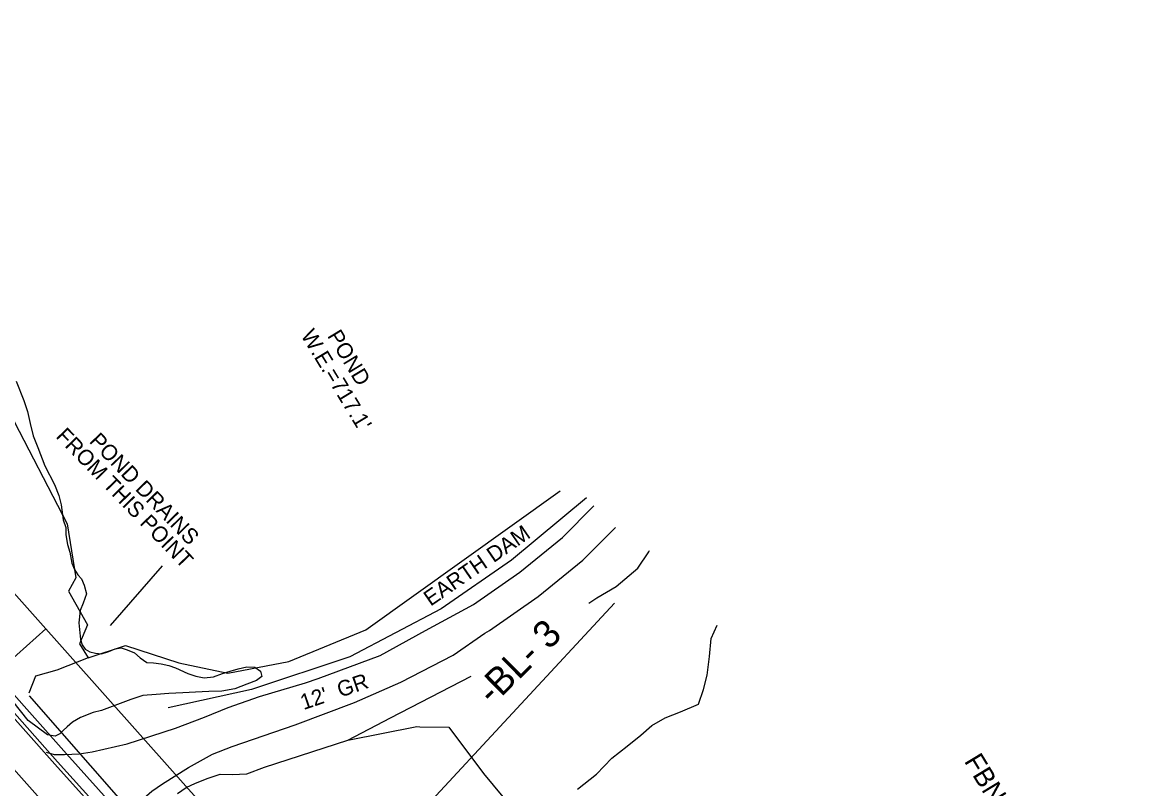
# Model space of a CAD drawing. Extents: x 1498375 to 1499839, y 700490 to 702854.
# Drawn here: x 1498616.6 to 1498900.7, y 702558.4 to 702754.8 of the extents above; entities that cross this region are included whole.
import ezdxf

# ---------------------------------------------------------------- set-up
doc = ezdxf.new("R2010")
doc.units = 0
for name, color, linetype in [('Exist Horizontal Alignment', 7, 'Continuous'), ('Exist Horizontal Baseline Alignment Station Label', 7, 'Continuous'), ('Exist Hydro Stream or Body of Water', 7, 'Continuous'), ('Exist Hydro Stream or Body of Water Leader', 7, 'Continuous'), ('Exist Hydro Stream or Body of Water Text', 7, 'Continuous'), ('Exist Other Culture Dam', 7, 'Continuous'), ('Exist Other Culture Dam Text', 7, 'Continuous'), ('Exist Property Owner Text', 7, 'Continuous'), ('Exist Right of Way Line', 7, 'Continuous'), ('Exist Right of Way Width CELL', 7, 'Continuous'), ('Exist Roads EOP', 7, 'Continuous'), ('Exist Roads Soil', 7, 'Continuous'), ('Exist Roads Soil Text', 7, 'Continuous'), ('Exist Structure Minor Pipes RCP 15 Inch', 7, 'Continuous'), ('Exist Utilities Telephone UG Cable', 7, 'Continuous'), ('Exist Vegetation Hedge Row', 7, 'Continuous'), ('Exist Vegetation Woods Line', 7, 'Continuous')]:
    doc.layers.add(name, color=color, linetype=linetype)

msp = doc.modelspace()

# ---------------------------------------------------------------- linework, layer by layer
at = {"layer": 'Exist Horizontal Alignment'}
msp.add_line((1498462.01, 702734.88), (1498796.99, 702358.25), dxfattribs=at)
at = {"layer": 'Exist Horizontal Baseline Alignment Station Label'}
msp.add_line((1498656.97, 702485.84), (1498768.4, 702605.94), dxfattribs=at)
at = {"layer": 'Exist Hydro Stream or Body of Water'}
for points in [[(1498613.4, 702654.84), (1498628.21, 702626.31), (1498630.4, 702612.48), (1498628.51, 702609.01), (1498633.37, 702600.4), (1498631.33, 702595.51), (1498633.57, 702592), (1498643.13, 702595.13), (1498656.81, 702590.65), (1498669.3, 702588.07), (1498684.93, 702591), (1498704.71, 702599.15), (1498754.44, 702634.77)], [(1498633.57, 702592), (1498625.53, 702588.81), (1498620.02, 702587.23), (1498618.32, 702582.91)]]:
    msp.add_lwpolyline(points, dxfattribs=at)
at = {"layer": 'Exist Hydro Stream or Body of Water Leader'}
msp.add_lwpolyline([(1498639.27, 702600.23), (1498652.59, 702615.54)], dxfattribs=at)
at = {"layer": 'Exist Other Culture Dam'}
msp.add_lwpolyline([(1498761.24, 702632.94), (1498741.99, 702616.94), (1498723.98, 702604.49), (1498700.61, 702592.2), (1498675.42, 702583.88), (1498654.01, 702579.14)], dxfattribs=at)
at = {"layer": 'Exist Right of Way Line'}
msp.add_line((1498484.43, 702754.82), (1498819.41, 702378.18), dxfattribs=at)
at = {"layer": 'Exist Right of Way Width CELL'}
msp.add_line((1498622.69, 702599.36), (1498600.43, 702579.56), dxfattribs=at)
at = {"layer": 'Exist Roads EOP'}
msp.add_lwpolyline([(1498653.88, 702532.59), (1498624.99, 702564.68), (1498593.83, 702599.75), (1498561.87, 702636.22), (1498531.52, 702670.43), (1498499.26, 702706.7), (1498468.51, 702741.33)], dxfattribs=at)
at = {"layer": 'Exist Roads Soil'}
for points in [[(1498692.47, 702586.65), (1498708.37, 702592.53), (1498719.94, 702598.93), (1498732.28, 702605.63), (1498744.17, 702613.89), (1498755.03, 702622.79), (1498763.13, 702630.86)], [(1498735.15, 702598.32), (1498736.37, 702598.99), (1498748.87, 702607.66), (1498760.26, 702617.01), (1498768.6, 702625.31)], [(1498670.43, 702569.26), (1498686.6, 702574.77), (1498701.79, 702580.51), (1498713.64, 702585.7), (1498727.03, 702592.63), (1498735.15, 702598.32)], [(1498655.94, 702573.98), (1498663.34, 702576.75), (1498669.42, 702579.25), (1498677.43, 702582.02), (1498689.24, 702585.54), (1498692.47, 702586.65)], [(1498622.8, 702567.82), (1498624.83, 702567.19), (1498627.52, 702567.22), (1498631.23, 702567.33), (1498634.55, 702567.84), (1498643.57, 702569.94), (1498655.94, 702573.98)], [(1498644.48, 702543.72), (1498644.29, 702549), (1498645.31, 702552.27), (1498647.18, 702555.48), (1498649.83, 702557.76), (1498652.61, 702559.64), (1498659.23, 702563.88), (1498665.42, 702567.32), (1498670.43, 702569.26)]]:
    msp.add_lwpolyline(points, dxfattribs=at)
at = {"layer": 'Exist Structure Minor Pipes RCP 15 Inch'}
msp.add_lwpolyline([(1498618.47, 702582.21), (1498649.73, 702546.53)], dxfattribs=at)
at = {"layer": 'Exist Utilities Telephone UG Cable'}
for points in [[(1498478.31, 702731.8), (1498500, 702707.36), (1498532.27, 702671.1), (1498562.62, 702636.88), (1498594.58, 702600.41), (1498625.73, 702565.35), (1498657.7, 702529.85)], [(1498480.79, 702733.52), (1498502.24, 702709.35), (1498534.51, 702673.09), (1498564.87, 702638.87), (1498596.83, 702602.4), (1498627.97, 702567.35), (1498660.83, 702530.85), (1498690.32, 702497.9), (1498721.99, 702462.5), (1498751.79, 702428.93), (1498785.03, 702390.83)]]:
    msp.add_lwpolyline(points, dxfattribs=at)
at = {"layer": 'Exist Vegetation Hedge Row'}
for points in [[(1498761.83, 702605.97), (1498763.85, 702607.3), (1498768.85, 702610.24), (1498774.32, 702614.93), (1498777.14, 702619.09), (1498777.35, 702619.42)], [(1498700.08, 702570.87), (1498711.04, 702576.62), (1498731.64, 702587.23)]]:
    msp.add_lwpolyline(points, dxfattribs=at)
at = {"layer": 'Exist Vegetation Woods Line'}
for points in [[(1498615.13, 702662.82), (1498617.04, 702657.89), (1498618.05, 702655.06), (1498618.67, 702652.02), (1498619.48, 702648.86), (1498620.64, 702645.83), (1498622.44, 702641.18), (1498624.95, 702636.41), (1498626.08, 702633.52), (1498626.62, 702631.16), (1498627.15, 702627.28), (1498627.85, 702625.39), (1498627.79, 702623.48), (1498628.28, 702621.01), (1498628.84, 702619.01), (1498629.38, 702616.19), (1498630.01, 702614.56), (1498630.91, 702613.24), (1498631.83, 702612.21), (1498632.49, 702610.56), (1498633.09, 702608.34), (1498632.31, 702605.94), (1498631.53, 702604.05), (1498631.2, 702600.96), (1498631.6, 702596.65), (1498632.05, 702595.29), (1498632.75, 702594.21), (1498634.02, 702593.52), (1498635.46, 702593.13), (1498637, 702593), (1498638.82, 702593.62), (1498640.51, 702594.28), (1498642, 702594.54), (1498643.58, 702594.03), (1498645.38, 702593.28), (1498646.9, 702591.93), (1498648.6, 702590.75), (1498650.29, 702590.7), (1498652.27, 702590.44), (1498654.21, 702589.96), (1498655.9, 702589.43), (1498659.09, 702587.97), (1498661.13, 702587.29), (1498663.23, 702586.87), (1498665.65, 702587.08), (1498667.97, 702587.97), (1498669.89, 702588.57), (1498671.97, 702589.15), (1498674.16, 702589.69), (1498676.24, 702589.54), (1498677.71, 702588.55), (1498678.07, 702587.21), (1498676.71, 702586.18), (1498674.18, 702585.2), (1498671.11, 702584.02), (1498667.78, 702583.4), (1498664.46, 702583.32), (1498661.05, 702583.19), (1498657.8, 702583.03), (1498654.19, 702582.79), (1498651, 702582.58), (1498647.52, 702582.28), (1498644.44, 702581.31), (1498641.77, 702580.3), (1498636.93, 702578.44), (1498634.82, 702577.95), (1498631.57, 702576.67), (1498629.51, 702575.45), (1498628.21, 702574.25), (1498627.15, 702573.37), (1498626.27, 702572.51), (1498625.06, 702571.85), (1498623.15, 702572.23), (1498618.18, 702575.94), (1498607.96, 702588.7)], [(1498758.91, 702558.35), (1498763.79, 702562.12), (1498767.71, 702566.27), (1498771.66, 702569.36), (1498775.1, 702572.14), (1498777.99, 702574.65), (1498781.4, 702576.57), (1498785.27, 702578.11), (1498789.89, 702580.05), (1498791.22, 702583.81), (1498792.16, 702587.5), (1498792.71, 702592.32), (1498793.11, 702596.91), (1498794.65, 702600.37)], [(1498656.45, 702557.18), (1498658.65, 702558.73), (1498661.01, 702559.81), (1498664.32, 702561.09), (1498667.39, 702562.15), (1498670.44, 702562.07), (1498674.19, 702562.28), (1498678.69, 702563.91), (1498700.08, 702570.87), (1498717.71, 702574.35), (1498718.51, 702574.32), (1498725.98, 702574.23), (1498734.79, 702562.29), (1498742.72, 702552.87)]]:
    msp.add_lwpolyline(points, dxfattribs=at)

# ---------------------------------------------------------------- texts
at = {"layer": 'Exist Horizontal Baseline Alignment Station Label'}
msp.add_text('-BL- 3', height=7, rotation=44.6247, dxfattribs=at).set_placement((1498737.14, 702579.57))
at = {"layer": 'Exist Hydro Stream or Body of Water Text'}
for s, rotation, p in [("W.E.=717.1'", 301.2023, (1498687.91, 702674.61)), ('POND', 301.2023, (1498694.69, 702674.46)), ('FROM THIS POINT', 314.0644, (1498625.08, 702648.53)), ('POND DRAINS', 314.0644, (1498633.62, 702647.26))]:
    msp.add_text(s, height=4, rotation=rotation, dxfattribs=at).set_placement(p)
at = {"layer": 'Exist Other Culture Dam Text'}
msp.add_text('EARTH DAM', height=4, rotation=34.637, dxfattribs=at).set_placement((1498721.27, 702605.05))
at = {"layer": 'Exist Property Owner Text'}
msp.add_text('FBN DEVELOPERS, INC.', height=5, rotation=301.2023, dxfattribs=at).set_placement((1498857.83, 702565.5))
at = {"layer": 'Exist Roads Soil Text'}
msp.add_text("12'  GR", height=4, rotation=18.8178, dxfattribs=at).set_placement((1498688.72, 702578.55))

doc.saveas('drawing.dxf')
